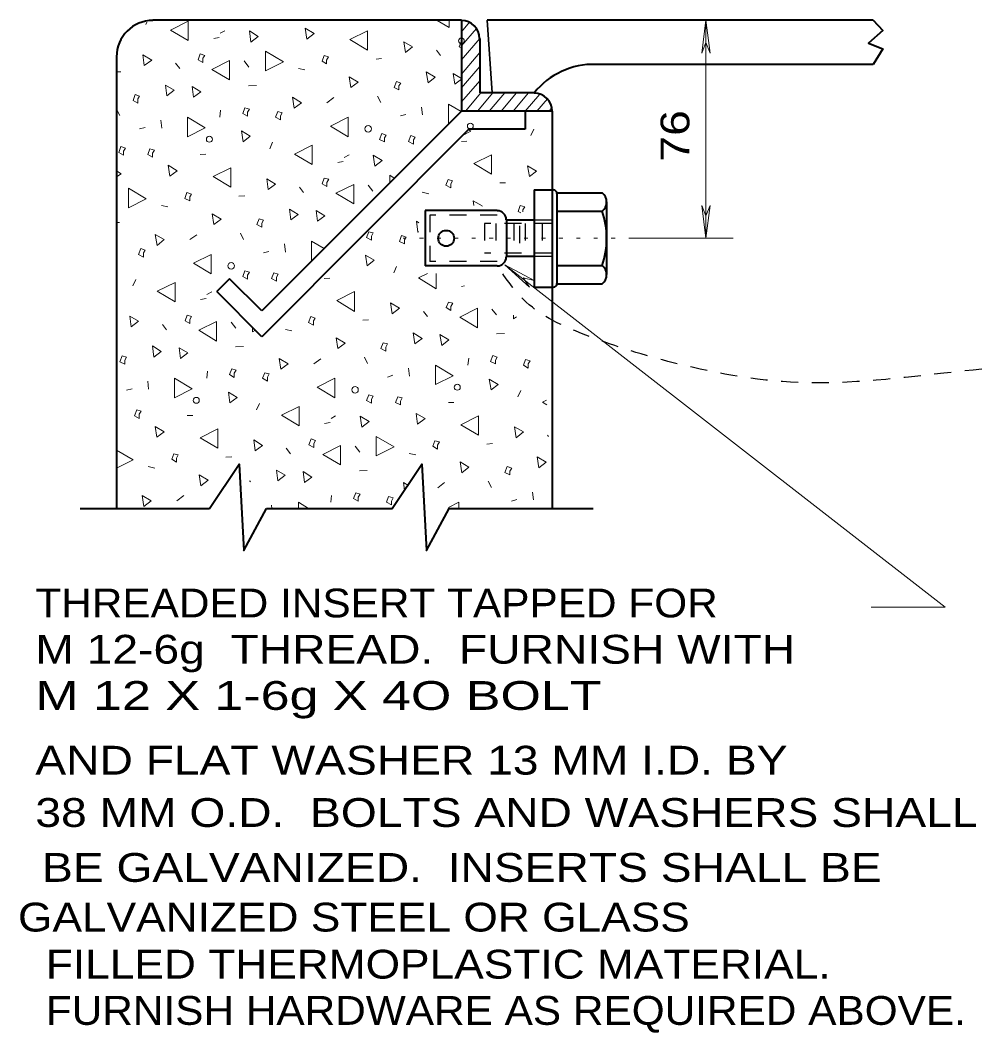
# Model space of a CAD drawing. Extents: x 312583 to 312854, y 144419 to 144597.
# Drawn here: x 312805.01 to 312830.52, y 144544.93 to 144571.65 of the extents above; entities that cross this region are included whole.
import ezdxf

# ---------------------------------------------------------------- set-up
doc = ezdxf.new("R2010")
doc.units = 0
doc.header["$LTSCALE"] = 0.3
doc.header["$PDMODE"] = 32
doc.header["$PDSIZE"] = 0.15
doc.linetypes.add('DOTTED', pattern=[1.5, 0.3, -1.2])
doc.linetypes.add('SHORT_DASHED', pattern=[2.7, 1.5, -1.2])
doc.layers.add('1', color=7, linetype='Continuous', lineweight=40)
doc.layers.add('2', color=7, linetype='Continuous', lineweight=13)

msp = doc.modelspace()

# ---------------------------------------------------------------- linework, layer by layer
at = {"layer": '1'}
for p, q in [((312816.654, 144571.6492), (312808.512, 144571.6492)), ((312816.654, 144571.6492), (312816.654, 144569.2496)), ((312827.5253, 144571.6492), (312817.3363, 144571.6492)), ((312817.137, 144571.1662), (312817.137, 144569.7326)), ((312807.5537, 144570.6909), (312807.5537, 144558.7692)), ((312827.5253, 144570.4839), (312820.2037, 144570.4839)), ((312818.5707, 144569.7326), (312817.137, 144569.7326)), ((312816.654, 144569.2496), (312811.387, 144563.9826)), ((312819.0537, 144569.2496), (312816.654, 144569.2496)), ((312818.333, 144569.2496), (312818.333, 144568.7742)), ((312819.0537, 144569.2496), (312819.0537, 144558.7692)), ((312816.8533, 144568.7742), (312811.387, 144563.3002)), ((312818.333, 144568.7742), (312816.8533, 144568.7742)), ((312818.5783, 144567.1719), (312819.0843, 144567.1719)), ((312818.5783, 144567.1719), (312818.5783, 144564.6036)), ((312819.1763, 144567.0952), (312820.3723, 144567.0952)), ((312819.1763, 144567.0799), (312819.1763, 144564.7032)), ((312820.4873, 144566.8576), (312820.4873, 144564.9409)), ((312815.6957, 144566.6276), (312815.6957, 144565.1709)), ((312817.597, 144566.6276), (312815.6957, 144566.6276)), ((312819.1763, 144566.6122), (312820.3723, 144566.6122)), ((312817.8423, 144566.3822), (312817.8423, 144565.4086)), ((312818.5783, 144566.3746), (312817.8423, 144566.3746)), ((312818.5783, 144565.4162), (312817.8423, 144565.4162)), ((312817.597, 144565.1709), (312815.6957, 144565.1709)), ((312819.1763, 144565.1786), (312820.3723, 144565.1786)), ((312810.536, 144564.8259), (312810.1987, 144564.4886)), ((312811.387, 144563.9826), (312810.536, 144564.8259)), ((312819.1763, 144564.6956), (312820.3723, 144564.6956)), ((312811.387, 144563.3002), (312810.1987, 144564.4886)), ((312818.5783, 144564.6036), (312819.0843, 144564.6036)), ((312806.5877, 144558.7692), (312810.007, 144558.7692))]:
    msp.add_line(p, q, dxfattribs=at)
at = {"layer": '1', "lineweight": 35}
msp.add_line((312817.4667, 144569.7326), (312817.3363, 144571.6492), dxfattribs=at)
at = {"layer": '1', "lineweight": 13}
for p, q in [((312816.8687, 144571.5956), (312816.654, 144571.3426)), ((312817.0527, 144571.4346), (312816.654, 144570.9746)), ((312817.137, 144571.1662), (312816.654, 144570.6066)), ((312817.137, 144570.7982), (312816.654, 144570.2309)), ((312817.137, 144570.4302), (312816.654, 144569.8629)), ((312817.137, 144570.0546), (312816.654, 144569.4949)), ((312817.1677, 144569.7326), (312816.7613, 144569.2496)), ((312817.482, 144569.7326), (312817.0757, 144569.2496)), ((312817.7963, 144569.7326), (312817.39, 144569.2496)), ((312818.1107, 144569.7326), (312817.7043, 144569.2496)), ((312818.425, 144569.7326), (312818.0187, 144569.2496)), ((312818.724, 144569.7019), (312818.333, 144569.2496)), ((312818.9233, 144569.5716), (312818.6473, 144569.2496)), ((312816.654, 144569.3799), (312816.654, 144569.3722)), ((312819.0383, 144569.3416), (312818.9617, 144569.2496))]:
    msp.add_line(p, q, dxfattribs=at)
at = {"layer": '1', "linetype": 'SHORT_DASHED', "lineweight": 25}
for p, q in [((312817.2597, 144566.2902), (312817.2597, 144565.5006)), ((312819.0537, 144566.2902), (312817.2597, 144566.2902)), ((312817.5587, 144566.2902), (312817.5587, 144565.5006)), ((312818.0417, 144566.2902), (312818.0417, 144565.5006)), ((312818.3407, 144566.2902), (312818.3407, 144565.5006)), ((312819.0537, 144566.3746), (312818.5783, 144566.3746)), ((312818.7853, 144566.2902), (312818.7853, 144565.5006)), ((312818.1873, 144566.2212), (312818.1873, 144565.5772)), ((312819.0537, 144565.5006), (312817.2597, 144565.5006)), ((312817.597, 144565.2859), (312815.8183, 144565.2859)), ((312819.0537, 144565.4162), (312818.5783, 144565.4162))]:
    msp.add_line(p, q, dxfattribs=at)
at = {"layer": '1', "linetype": 'DOTTED', "lineweight": 13}
msp.add_line((312821.1697, 144565.8992), (312815.113, 144565.8992), dxfattribs=at)
at = {"layer": '1'}
for points in [[(312827.5253, 144571.6492), (312827.7783, 144571.3809), (312827.395, 144571.0436), (312827.7783, 144570.8979), (312827.5253, 144570.4839)], [(312810.007, 144558.7692), (312810.789, 144559.9346), (312810.9117, 144557.6576), (312811.5097, 144558.7692)], [(312811.5097, 144558.7692), (312814.8293, 144558.7692), (312815.6113, 144559.9346), (312815.734, 144557.6576), (312816.332, 144558.7692), (312820.1347, 144558.7692)]]:
    msp.add_lwpolyline(points, dxfattribs=at)
at = {"layer": '1', "lineweight": 13}
msp.add_lwpolyline([(312816.8457, 144568.7589), (312816.8993, 144568.7206), (312816.7, 144568.6209)], dxfattribs=at)
at = {"layer": '1', "linetype": 'SHORT_DASHED', "lineweight": 25}
msp.add_lwpolyline([(312817.597, 144566.5049), (312815.8183, 144566.5049), (312815.8183, 144565.2859)], dxfattribs=at)
at = {"layer": '1'}
msp.add_circle((312816.2515, 144565.8954), 0.2102, dxfattribs=at)
for centre, radius, start, end in [((312808.5082, 144570.6871), 0.9583, 90, 180), ((312816.654, 144571.1662), 0.4792, 0, 90), ((312820.1532, 144568.4548), 2.0316, 88.63097, 141.1667), ((312818.5707, 144569.2496), 0.4792, 0, 90), ((312819.0805, 144567.0761), 0.0958, 0, 90), ((312820.1864, 144566.8537), 0.3009, 307.23717, 52.76282), ((312817.5989, 144566.3841), 0.2396, 0, 90), ((312818.2543, 144565.8954), 2.2331, 341.22405, 18.77595), ((312817.5989, 144565.4067), 0.2396, 270, 0), ((312820.1864, 144564.9371), 0.3009, 307.23718, 52.76283), ((312819.0805, 144564.6994), 0.0958, 270, 0)]:
    msp.add_arc(centre, radius, start, end, dxfattribs=at)
at = {"layer": '2'}
for p, q in [((312816.01, 144571.6416), (312816.332, 144571.4576)), ((312816.332, 144571.4576), (312816.332, 144571.6416)), ((312823.1093, 144571.6492), (312823.002, 144570.7829)), ((312823.1093, 144565.8992), (312823.1093, 144571.6492)), ((312823.1093, 144571.6492), (312823.2167, 144570.7829)), ((312808.351, 144571.5956), (312808.328, 144571.5342)), ((312810.283, 144571.3042), (312810.4133, 144571.3732)), ((312810.1143, 144571.1662), (312810.26, 144571.1969)), ((312815.9947, 144570.8596), (312816.102, 144570.7216)), ((312823.002, 144570.7829), (312823.1093, 144571.0589)), ((312823.2167, 144570.7829), (312823.1093, 144571.0589)), ((312810.9193, 144570.5759), (312811.042, 144570.4149)), ((312814.4, 144570.6219), (312814.5457, 144570.6372)), ((312807.5537, 144570.2846), (312807.661, 144570.2922)), ((312809.11, 144570.5146), (312809.2173, 144570.3766)), ((312812.353, 144570.3766), (312812.5217, 144570.3382)), ((312816.4777, 144569.9626), (312816.654, 144570.0929)), ((312811.0343, 144569.9166), (312811.249, 144569.9319)), ((312813.2883, 144569.6099), (312813.1043, 144569.4719)), ((312814.4383, 144569.6482), (312814.5227, 144569.4796)), ((312810.2753, 144569.0886), (312810.2983, 144569.2802)), ((312815.6037, 144569.3569), (312815.6267, 144569.1499)), ((312816.6463, 144569.2419), (312816.3167, 144569.4336)), ((312808.719, 144569.0119), (312808.742, 144568.8049)), ((312815.044, 144569.1269), (312815.1897, 144569.1652)), ((312808.1593, 144568.7819), (312808.305, 144568.8202)), ((312818.563, 144568.7742), (312818.4863, 144568.6056)), ((312811.6707, 144568.4292), (312811.594, 144568.2606)), ((312816.654, 144568.4522), (312816.7997, 144568.4599)), ((312809.7617, 144568.1072), (312809.9073, 144568.1149)), ((312813.388, 144567.8926), (312813.5337, 144567.9232)), ((312813.5567, 144568.0306), (312813.687, 144568.0996)), ((312814.7603, 144567.5629), (312814.7603, 144567.3559)), ((312814.883, 144567.4862), (312814.7603, 144567.5629)), ((312817.666, 144567.3559), (312817.8193, 144567.3636)), ((312812.376, 144567.2409), (312812.4833, 144567.1029)), ((312814.193, 144567.3022), (312814.3157, 144567.1412)), ((312815.619, 144567.1106), (312815.7953, 144567.0722)), ((312810.7813, 144567.0109), (312810.9347, 144567.0186)), ((312808.7343, 144566.7656), (312808.903, 144566.7272)), ((312818.2717, 144566.5969), (312818.2793, 144566.6429)), ((312823.002, 144566.7656), (312823.1093, 144566.4896)), ((312823.1093, 144565.8992), (312823.002, 144566.7656)), ((312823.2167, 144566.7656), (312823.1093, 144566.4896)), ((312823.1093, 144565.8992), (312823.2167, 144566.7656)), ((312807.5537, 144566.3132), (312807.6303, 144566.3132)), ((312810.8197, 144566.0296), (312810.904, 144565.8609)), ((312815.504, 144566.0602), (312815.527, 144566.0679)), ((312809.6697, 144565.9912), (312809.4857, 144565.8609)), ((312811.985, 144565.7459), (312812.008, 144565.5312)), ((312813.0277, 144565.6232), (312812.698, 144565.8226)), ((312821.1697, 144565.8992), (312823.83, 144565.8992)), ((312811.4253, 144565.5082), (312811.571, 144565.5466)), ((312814.9443, 144565.1556), (312814.8677, 144564.9869)), ((312815.987, 144564.5652), (312815.987, 144564.9639)), ((312829.4267, 144556.1626), (312817.804, 144565.1939)), ((312817.804, 144565.1939), (312818.448, 144564.6036)), ((312817.804, 144565.1939), (312818.5707, 144564.7799)), ((312808.0597, 144564.8106), (312807.983, 144564.6419)), ((312813.0353, 144564.8336), (312813.181, 144564.8412)), ((312818.448, 144564.6036), (312818.287, 144564.8566)), ((312818.5707, 144564.7799), (312818.287, 144564.8566)), ((312809.938, 144564.4119), (312810.0683, 144564.4809)), ((312816.654, 144564.6266), (312816.7383, 144564.6419)), ((312809.7693, 144564.2816), (312809.915, 144564.3046)), ((312815.6497, 144563.9672), (312815.757, 144563.8292)), ((312817.459, 144564.0286), (312817.5817, 144563.8752)), ((312808.765, 144563.6222), (312808.8723, 144563.4842)), ((312810.5743, 144563.6836), (312810.697, 144563.5226)), ((312814.0473, 144563.7372), (312814.2007, 144563.7449)), ((312812.008, 144563.4919), (312812.1767, 144563.4536)), ((312817.5817, 144563.3769), (312817.7887, 144563.3846)), ((312810.6893, 144563.0319), (312810.904, 144563.0396)), ((312812.9433, 144562.7176), (312812.7593, 144562.5872)), ((312814.0933, 144562.7636), (312814.1777, 144562.5949)), ((312816.8227, 144562.5489), (312816.8457, 144562.7329)), ((312809.9303, 144562.2039), (312809.9533, 144562.3879)), ((312814.699, 144562.2346), (312814.8447, 144562.2806)), ((312815.2587, 144562.4722), (312815.2817, 144562.2576)), ((312808.374, 144562.1272), (312808.397, 144561.9126)), ((312807.8143, 144561.8896), (312807.96, 144561.9279)), ((312818.218, 144561.8819), (312818.1413, 144561.7132)), ((312811.3257, 144561.5369), (312811.249, 144561.3682)), ((312816.309, 144561.5676), (312816.4547, 144561.5676)), ((312809.4167, 144561.2226), (312809.5623, 144561.2226)), ((312813.2117, 144561.1459), (312813.3343, 144561.2149)), ((312813.043, 144561.0079), (312813.1887, 144561.0386)), ((312818.9233, 144560.7012), (312818.954, 144560.6629)), ((312813.848, 144560.4099), (312813.9707, 144560.2566)), ((312817.321, 144560.4636), (312817.4743, 144560.4789)), ((312810.4363, 144560.1186), (312810.5897, 144560.1339)), ((312812.031, 144560.3562), (312812.1383, 144560.2106)), ((312815.274, 144560.2182), (312815.4503, 144560.1799)), ((312808.3893, 144559.8732), (312808.558, 144559.8349)), ((312813.963, 144559.7582), (312814.17, 144559.7736)), ((312816.2093, 144559.4516), (312816.033, 144559.3136)), ((312817.3593, 144559.4899), (312817.4513, 144559.3212)), ((312809.3247, 144559.1066), (312809.1407, 144558.9686)), ((312813.204, 144558.9302), (312813.227, 144559.1142)), ((312818.5323, 144559.1986), (312818.5553, 144558.9916)), ((312811.64, 144558.8536), (312811.6477, 144558.7692)), ((312812.353, 144558.9302), (312812.353, 144558.7692)), ((312812.6213, 144558.7692), (312812.353, 144558.9302)), ((312817.9727, 144558.9609), (312818.1183, 144559.0069)), ((312829.4267, 144556.1626), (312827.4717, 144556.1626))]:
    msp.add_line(p, q, dxfattribs=at)
for points in [[(312809.4397, 144571.1126), (312809.4397, 144571.6262), (312808.972, 144571.3886)], [(312811.0957, 144571.0742), (312811.2873, 144571.2199), (312811.0573, 144571.3656)], [(312812.5753, 144571.1509), (312812.767, 144571.2966), (312812.5293, 144571.4422)], [(312814.1777, 144570.8596), (312814.1777, 144571.3732), (312813.71, 144571.1432)], [(312811.4867, 144570.8366), (312811.4867, 144570.3152), (312811.9543, 144570.5529)], [(312815.1743, 144570.7982), (312815.366, 144570.9439), (312815.136, 144571.0819)], [(312808.282, 144570.4532), (312808.4813, 144570.5989), (312808.2437, 144570.7369)], [(312809.8307, 144570.6449), (312809.8767, 144570.7216), (312809.7617, 144570.7599), (312809.708, 144570.6066), (312809.8307, 144570.5376)], [(312810.536, 144570.0776), (312810.536, 144570.5912), (312810.0683, 144570.3536)], [(312813.0967, 144570.5989), (312813.1427, 144570.6832), (312813.0277, 144570.7216), (312812.974, 144570.5682), (312813.0967, 144570.4992)], [(312815.7723, 144570.0009), (312815.964, 144570.1466), (312815.7263, 144570.2846)], [(312813.733, 144569.8706), (312813.9323, 144570.0162), (312813.6947, 144570.1542)], [(312815.0057, 144569.9166), (312815.0517, 144569.9932), (312814.9367, 144570.0316), (312814.8753, 144569.8782), (312815.0057, 144569.8092)], [(312808.88, 144569.6559), (312809.0717, 144569.8016), (312808.8417, 144569.9396)], [(312809.5853, 144569.6176), (312809.777, 144569.7632), (312809.547, 144569.9012)], [(312808.1133, 144569.5716), (312808.1593, 144569.6482), (312808.0443, 144569.6866), (312807.9907, 144569.5332), (312808.1133, 144569.4642)], [(312812.238, 144569.3262), (312812.4297, 144569.4719), (312812.192, 144569.6176)], [(312811.0037, 144569.2266), (312811.0573, 144569.3032), (312810.9347, 144569.3416), (312810.881, 144569.1882), (312811.0037, 144569.1192)], [(312811.8777, 144569.1269), (312811.9237, 144569.2036), (312811.8087, 144569.2419), (312811.7473, 144569.0886), (312811.8777, 144569.0196)], [(312809.4243, 144569.0886), (312809.4243, 144568.5749), (312809.892, 144568.8126)], [(312813.664, 144568.5749), (312813.664, 144569.0886), (312813.1963, 144568.8586)], [(312810.8887, 144568.4446), (312811.0803, 144568.5902), (312810.8503, 144568.7282)], [(312814.6223, 144568.5442), (312814.6683, 144568.6209), (312814.5533, 144568.6592), (312814.492, 144568.5059), (312814.6223, 144568.4369)], [(312815.389, 144568.4906), (312815.435, 144568.5672), (312815.32, 144568.6056), (312815.2587, 144568.4522), (312815.389, 144568.3832)], [(312807.7377, 144568.1916), (312807.7837, 144568.2759), (312807.661, 144568.3142), (312807.6073, 144568.1609), (312807.7377, 144568.0919)], [(312808.4967, 144568.1456), (312808.5503, 144568.2222), (312808.4277, 144568.2606), (312808.374, 144568.1072), (312808.4967, 144568.0382)], [(312812.7133, 144567.8389), (312812.7133, 144568.3526), (312812.2457, 144568.1149)], [(312814.3693, 144567.8006), (312814.561, 144567.9462), (312814.3233, 144568.0919)], [(312817.4513, 144567.5859), (312817.4513, 144568.0996), (312816.9837, 144567.8696)], [(312808.9567, 144567.5322), (312809.1483, 144567.6779), (312808.9107, 144567.8236)], [(312810.5667, 144567.2409), (312810.5667, 144567.7546), (312810.099, 144567.5246)], [(312818.448, 144567.5246), (312818.6397, 144567.6702), (312818.402, 144567.8082)], [(312811.5557, 144567.1796), (312811.7473, 144567.3252), (312811.5173, 144567.4632)], [(312813.1043, 144567.3712), (312813.1503, 144567.4556), (312813.0353, 144567.4862), (312812.974, 144567.3329), (312813.1043, 144567.2639)], [(312816.3703, 144567.3329), (312816.4163, 144567.4096), (312816.3013, 144567.4479), (312816.24, 144567.2946), (312816.3703, 144567.2256)], [(312807.868, 144567.2179), (312807.868, 144566.7042), (312808.3357, 144566.9342)], [(312809.4857, 144566.9879), (312809.5317, 144567.0646), (312809.409, 144567.1029), (312809.3553, 144566.9496), (312809.4857, 144566.8806)], [(312813.8097, 144566.8039), (312813.8097, 144567.3176), (312813.342, 144567.0876)], [(312810.122, 144566.2596), (312810.3137, 144566.3976), (312810.076, 144566.5432)], [(312812.1537, 144566.3822), (312812.3453, 144566.5279), (312812.1153, 144566.6659)], [(312812.859, 144566.3439), (312813.0507, 144566.4896), (312812.8207, 144566.6276)], [(312811.387, 144566.2979), (312811.433, 144566.3746), (312811.318, 144566.4129), (312811.2567, 144566.2596), (312811.387, 144566.1906)], [(312814.2773, 144565.9529), (312814.3233, 144566.0372), (312814.2083, 144566.0679), (312814.147, 144565.9146), (312814.2773, 144565.8456)], [(312808.6193, 144565.7076), (312808.811, 144565.8609), (312808.5733, 144565.9989)], [(312815.1513, 144565.8532), (312815.1973, 144565.9299), (312815.0747, 144565.9682), (312815.021, 144565.8149), (312815.1513, 144565.7459)], [(312808.259, 144565.5082), (312808.305, 144565.5849), (312808.19, 144565.6232), (312808.1287, 144565.4699), (312808.259, 144565.4009)], [(312810.0453, 144564.9562), (312810.0453, 144565.4699), (312809.5777, 144565.2399)], [(312814.1623, 144565.1709), (312814.354, 144565.3166), (312814.124, 144565.4546)], [(312811.0037, 144564.9256), (312811.0573, 144565.0022), (312810.9347, 144565.0406), (312810.881, 144564.8872), (312811.0037, 144564.8182)], [(312811.7703, 144564.8719), (312811.8163, 144564.9486), (312811.7013, 144564.9869), (312811.64, 144564.8336), (312811.7703, 144564.7646)], [(312809.0947, 144564.2202), (312809.0947, 144564.7339), (312808.627, 144564.5039)], [(312813.8327, 144563.9672), (312813.8327, 144564.4886), (312813.365, 144564.2509)], [(312814.8293, 144563.9059), (312815.021, 144564.0516), (312814.7833, 144564.1896)], [(312816.378, 144564.0976), (312816.424, 144564.1819), (312816.309, 144564.2126), (312816.2477, 144564.0669), (312816.378, 144563.9902)], [(312817.0757, 144563.5302), (312817.0757, 144564.0516), (312816.608, 144563.8139)], [(312807.937, 144563.5609), (312808.1287, 144563.7066), (312807.8987, 144563.8446)], [(312809.4857, 144563.7526), (312809.5317, 144563.8369), (312809.4167, 144563.8676), (312809.363, 144563.7219), (312809.4857, 144563.6452)], [(312810.191, 144563.1852), (312810.191, 144563.6989), (312809.7233, 144563.4689)], [(312812.7517, 144563.7142), (312812.7977, 144563.7909), (312812.6827, 144563.8292), (312812.6213, 144563.6759), (312812.7517, 144563.6069)], [(312815.4273, 144563.1086), (312815.619, 144563.2542), (312815.3813, 144563.3999)], [(312816.1327, 144563.0702), (312816.3243, 144563.2159), (312816.0867, 144563.3616)], [(312813.388, 144562.9859), (312813.5873, 144563.1316), (312813.3497, 144563.2696)], [(312814.6607, 144563.0242), (312814.7067, 144563.1086), (312814.5917, 144563.1392), (312814.5303, 144562.9859), (312814.6607, 144562.9169)], [(312808.535, 144562.7636), (312808.7267, 144562.9092), (312808.4967, 144563.0549)], [(312809.2403, 144562.7252), (312809.432, 144562.8709), (312809.202, 144563.0089)], [(312817.551, 144562.6792), (312817.597, 144562.7636), (312817.482, 144562.8019), (312817.4207, 144562.6486), (312817.551, 144562.5796)], [(312807.7683, 144562.6792), (312807.8143, 144562.7636), (312807.6993, 144562.7942), (312807.638, 144562.6409), (312807.7683, 144562.5719)], [(312811.8853, 144562.4416), (312812.0847, 144562.5872), (312811.847, 144562.7252)], [(312815.9717, 144562.5489), (312815.9717, 144562.0352), (312816.4393, 144562.2652)], [(312818.4173, 144562.5796), (312818.471, 144562.6639), (312818.3483, 144562.6946), (312818.2947, 144562.5489), (312818.4173, 144562.4722)], [(312810.6587, 144562.3342), (312810.7123, 144562.4186), (312810.5897, 144562.4492), (312810.536, 144562.3036), (312810.6587, 144562.2269)], [(312811.5327, 144562.2346), (312811.5787, 144562.3189), (312811.4637, 144562.3496), (312811.4023, 144562.2039), (312811.5327, 144562.1272)], [(312809.0793, 144562.2039), (312809.0793, 144561.6902), (312809.547, 144561.9202)], [(312813.3113, 144561.6826), (312813.3113, 144562.2039), (312812.8437, 144561.9662)], [(312817.436, 144561.8972), (312817.6277, 144562.0429), (312817.39, 144562.1809)], [(312810.5437, 144561.5522), (312810.7353, 144561.6979), (312810.5053, 144561.8359)], [(312814.2773, 144561.6519), (312814.3233, 144561.7286), (312814.2083, 144561.7669), (312814.147, 144561.6136), (312814.2773, 144561.5446)], [(312815.044, 144561.5982), (312815.09, 144561.6826), (312814.975, 144561.7132), (312814.9137, 144561.5676), (312815.044, 144561.4986)], [(312808.1517, 144561.2532), (312808.1977, 144561.3376), (312808.0827, 144561.3682), (312808.0213, 144561.2149), (312808.1517, 144561.1459)], [(312812.3683, 144560.9466), (312812.3683, 144561.4602), (312811.9007, 144561.2302)], [(312814.0243, 144560.9159), (312814.216, 144561.0616), (312813.9783, 144561.1996)], [(312815.4963, 144560.9926), (312815.6957, 144561.1382), (312815.458, 144561.2762)], [(312817.1063, 144560.7012), (312817.1063, 144561.2149), (312816.6387, 144560.9772)], [(312808.6117, 144560.6476), (312808.8033, 144560.7932), (312808.5657, 144560.9312)], [(312810.2217, 144560.3562), (312810.2217, 144560.8699), (312809.754, 144560.6322)], [(312814.4077, 144560.6706), (312814.4077, 144560.1569), (312814.8753, 144560.3946)], [(312818.103, 144560.6322), (312818.2947, 144560.7856), (312818.057, 144560.9236)], [(312811.2107, 144560.2872), (312811.4023, 144560.4329), (312811.1723, 144560.5786)], [(312812.7593, 144560.4789), (312812.8053, 144560.5632), (312812.6903, 144560.6016), (312812.629, 144560.4482), (312812.7593, 144560.3792)], [(312813.4647, 144559.9192), (312813.4647, 144560.4329), (312812.997, 144560.1952)], [(312816.0253, 144560.4406), (312816.0713, 144560.5249), (312815.9563, 144560.5556), (312815.895, 144560.4099), (312816.0253, 144560.3332)], [(312809.133, 144560.0956), (312809.179, 144560.1799), (312809.064, 144560.2106), (312809.0103, 144560.0649), (312809.133, 144559.9882)], [(312816.6617, 144559.7122), (312816.8533, 144559.8579), (312816.6233, 144559.9959)], [(312817.9343, 144559.7506), (312817.9803, 144559.8349), (312817.8577, 144559.8732), (312817.804, 144559.7199), (312817.9343, 144559.6509)], [(312818.6933, 144559.8426), (312818.8927, 144559.9882), (312818.655, 144560.1262)], [(312809.777, 144559.3672), (312809.9687, 144559.5129), (312809.731, 144559.6509)], [(312811.8087, 144559.4976), (312812.0003, 144559.6432), (312811.7703, 144559.7812)], [(312812.514, 144559.4516), (312812.7057, 144559.5972), (312812.4757, 144559.7429)], [(312808.2743, 144558.8229), (312808.466, 144558.9686), (312808.2283, 144559.1066)], [(312813.9323, 144559.0682), (312813.9783, 144559.1449), (312813.8633, 144559.1832), (312813.802, 144559.0299), (312813.9323, 144558.9609)], [(312814.8063, 144558.9609), (312814.8523, 144559.0452), (312814.7297, 144559.0836), (312814.676, 144558.9302), (312814.8063, 144558.8612)]]:
    msp.add_lwpolyline(points, close=True, dxfattribs=at)
for points in [[(312816.654, 144571.1049), (312816.5927, 144570.9516), (312816.654, 144570.9209)], [(312816.654, 144570.1159), (312816.4393, 144570.2462), (312816.4777, 144569.9626)], [(312807.546, 144569.3032), (312807.5537, 144569.3032), (312807.638, 144569.1346)], [(312816.3167, 144569.4336), (312816.3167, 144568.9199), (312816.332, 144568.9276)], [(312807.5537, 144567.5169), (312807.6687, 144567.6012), (312807.5537, 144567.6779)], [(312817.1907, 144566.7426), (312817.1983, 144566.7502), (312816.9683, 144566.8882), (312816.9837, 144566.7579)], [(312818.2793, 144566.6429), (312818.3253, 144566.7272), (312818.2027, 144566.7579), (312818.149, 144566.6046), (312818.218, 144566.5662)], [(312815.527, 144566.3056), (312815.4657, 144566.3439), (312815.504, 144566.0602)], [(312812.698, 144565.8226), (312812.698, 144565.3012), (312812.7133, 144565.3166)], [(312815.757, 144564.9716), (312815.5193, 144564.8489), (312815.987, 144564.5652)], [(312818.0263, 144563.8676), (312818.0263, 144563.7756), (312818.1107, 144563.8216)], [(312811.1417, 144563.5456), (312811.1417, 144563.4306), (312811.2183, 144563.4689)], [(312818.9003, 144561.6289), (312818.793, 144561.5752), (312818.908, 144561.5062)], [(312807.5537, 144559.8272), (312807.9907, 144560.0496), (312807.5537, 144560.3102)], [(312811.0727, 144559.4669), (312811.088, 144559.4899), (312811.0573, 144559.4976)], [(312815.2433, 144559.3826), (312815.1207, 144559.4516), (312815.1513, 144559.2522)], [(312816.585, 144558.7692), (312816.585, 144558.9302), (312816.3167, 144558.7922)]]:
    msp.add_lwpolyline(points, dxfattribs=at)
for centre, radius in [((312814.1911, 144568.784), 0.0865), ((312816.89, 144568.855), 0.0784), ((312810.001, 144568.5094), 0.0784), ((312810.5738, 144565.1667), 0.0865), ((312816.5444, 144561.9661), 0.0784), ((312813.8455, 144561.8951), 0.0865), ((312809.6554, 144561.6205), 0.0784)]:
    msp.add_circle(centre, radius, dxfattribs=at)
at = {"layer": '2', "linetype": 'SHORT_DASHED', "lineweight": 25}
msp.add_spline([(312835.836, 144563.8752), (312833.766, 144563.0396), (312829.6413, 144562.3649), (312825.5627, 144562.0889), (312822.105, 144562.6486), (312819.8663, 144563.3692), (312818.3637, 144564.2126), (312817.597, 144565.1709)], degree=3, dxfattribs=at)
at = {"layer": '2'}
msp.add_point((312816.654, 144571.1049), dxfattribs=at)

# ---------------------------------------------------------------- texts
at = {"layer": '2', "width": 1.2}
msp.add_text('76 ', height=0.76, rotation=90, dxfattribs=at).set_placement((312822.672, 144567.9205))
at = {"layer": '2'}
for s, width, p in [('THREADED INSERT TAPPED FOR', 1.1, (312805.407, 144555.8932)), ('M 12-6g  THREAD.  FURNISH WITH', 1.2, (312805.407, 144554.6732)), ('M 12 X 1-6g X 4O BOLT ', 1.35, (312805.407, 144553.4532)), ('AND FLAT WASHER 13 MM I.D. BY', 1.2, (312805.407, 144551.7456)), ('38 MM O.D.  BOLTS AND WASHERS SHALL', 1.2, (312805.407, 144550.3656)), ('BE GALVANIZED.  INSERTS SHALL BE', 1.2, (312805.5833, 144548.9166)), (' GALVANIZED STEEL OR GLASS', 1.15, (312804.625, 144547.6056)), ('FILLED THERMOPLASTIC MATERIAL.', 1.15, (312805.683, 144546.3636)), ('FURNISH HARDWARE AS REQUIRED ABOVE.', 1.1, (312805.683, 144545.1436))]:
    msp.add_text(s, height=0.76, dxfattribs=dict(at, width=width)).set_placement(p)

doc.saveas('drawing.dxf')
